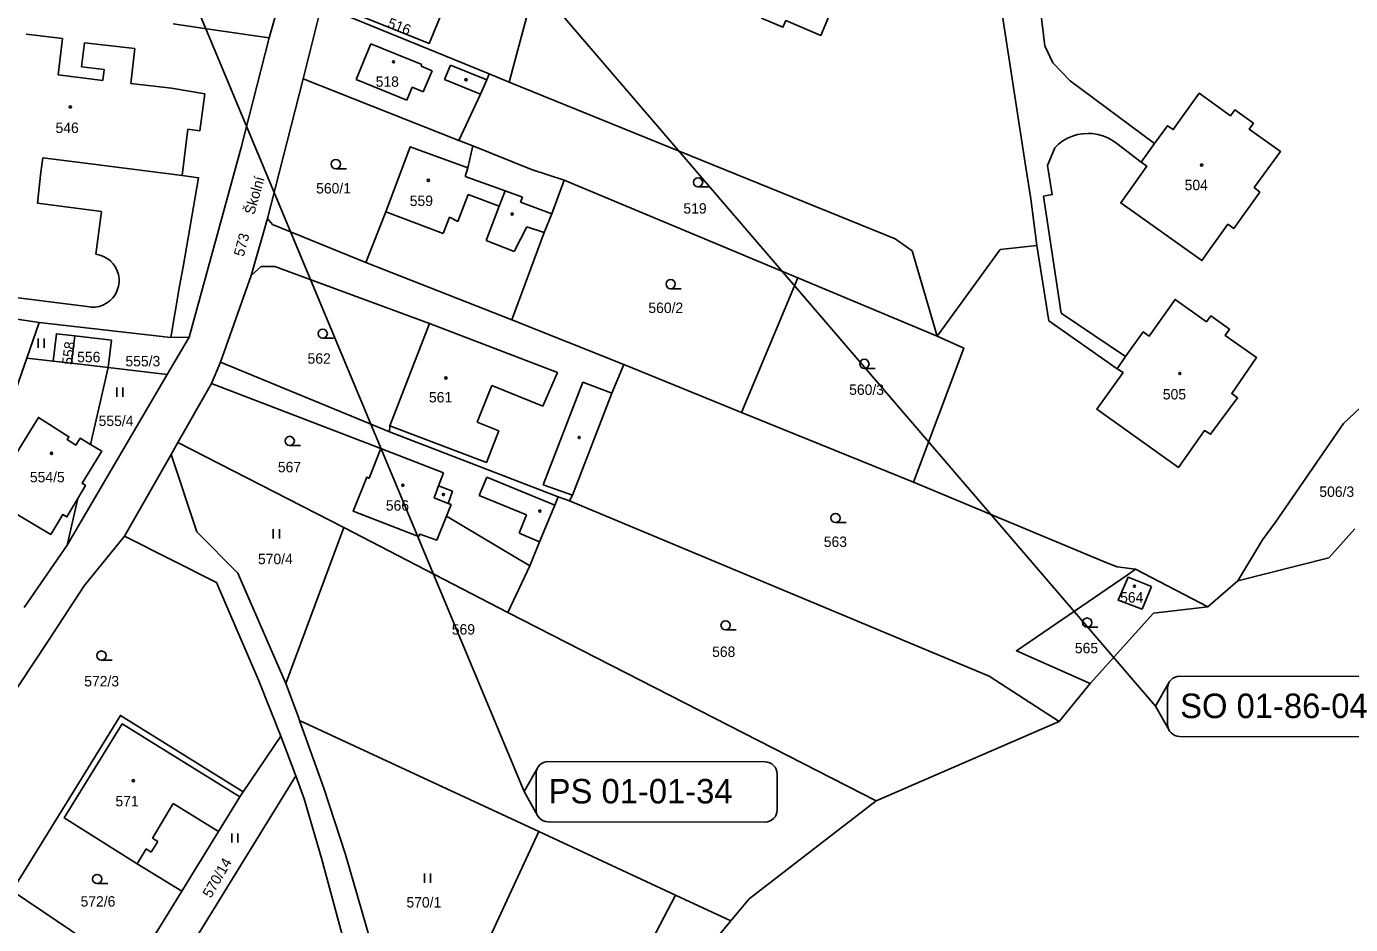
# Model space of a CAD drawing. Extents: x -558500 to -557517, y -1073973 to -1073051.
# Drawn here: x -558126.2 to -557909.9, y -1073687.1 to -1073540.5 of the extents above; entities that cross this region are included whole.
import ezdxf

# ---------------------------------------------------------------- set-up
doc = ezdxf.new("R2010")
doc.units = 0
for name, color, linetype in [('Hranice parcel', 7, 'Continuous'), ('Parcelní čísla', 7, 'Continuous'), ('Pop  PČ popisy', 7, 'Continuous'), ('Vnitřní kresba', 7, 'Continuous'), ('Vrstva 28', 7, 'Continuous'), ('Značky budov', 7, 'Continuous'), ('Značky kultur', 7, 'Continuous')]:
    doc.layers.add(name, color=color, linetype=linetype)

msp = doc.modelspace()

# ---------------------------------------------------------------- linework, layer by layer
at = {"layer": 'Hranice parcel'}
for p, q in [((-558079.12, -1073516.08), (-558086.54, -1073542.34)), ((-558078.01, -1073537.04), (-558080.96, -1073549.01)), ((-558078.01, -1073537.04), (-558050.57, -1073548.21)), ((-558080.96, -1073549.01), (-558086.83, -1073571.83)), ((-558080.96, -1073549.01), (-558055.56, -1073559.09)), ((-558050.57, -1073548.21), (-558047.33, -1073549.53)), ((-558055.56, -1073559.09), (-558053.26, -1073559.97)), ((-557944.07, -1073562.64), (-557948.05, -1073559.56)), ((-557941.9, -1073559.58), (-557944.07, -1073562.64)), ((-558038.36, -1073565.55), (-558000.16, -1073581.51)), ((-558086.83, -1073571.83), (-558089.47, -1073581.15)), ((-558070.72, -1073578.99), (-558046.87, -1073588.38)), ((-558089.47, -1073581.15), (-558094.5, -1073595.31)), ((-558009.36, -1073603.49), (-558000.16, -1073581.51)), ((-558000.16, -1073581.51), (-557977.41, -1073591.02)), ((-558169.56, -1073582.12), (-558124.1, -1073588.8)), ((-558146.72, -1073582.31), (-558116.26, -1073586.22)), ((-558046.87, -1073588.38), (-558028.58, -1073595.68)), ((-558124.1, -1073588.8), (-558126.13, -1073594.62)), ((-558124.1, -1073588.8), (-558102.62, -1073591.27)), ((-558118.29, -1073590.98), (-558118.81, -1073595.47)), ((-558099.6, -1073591.18), (-558103.17, -1073597.28)), ((-558102.62, -1073591.27), (-558099.6, -1073591.18)), ((-558121.8, -1073595.12), (-558126.13, -1073594.62)), ((-557946.67, -1073594.38), (-557948, -1073596.35)), ((-558121.8, -1073595.12), (-558118.81, -1073595.47)), ((-558118.81, -1073595.47), (-558112.83, -1073596.16)), ((-558115.73, -1073608.72), (-558112.83, -1073596.16)), ((-558112.83, -1073596.16), (-558103.17, -1073597.28)), ((-558094.5, -1073595.31), (-558095.93, -1073598.78)), ((-558094.5, -1073595.31), (-558066.88, -1073606.68)), ((-558028.58, -1073595.68), (-558009.36, -1073603.49)), ((-558103.17, -1073597.28), (-558119.53, -1073625.2)), ((-558095.93, -1073598.78), (-558101.44, -1073608.4)), ((-557981.3, -1073614.89), (-558009.36, -1073603.49)), ((-558066.88, -1073606.68), (-558039.3, -1073617.26)), ((-558101.44, -1073608.4), (-558102.56, -1073610.37)), ((-558101.44, -1073608.4), (-558074.34, -1073622.3)), ((-558102.56, -1073610.37), (-558110.18, -1073623.69)), ((-558119.53, -1073625.2), (-558117.76, -1073617.53)), ((-558039.3, -1073617.26), (-558037.5, -1073617.95)), ((-558074.34, -1073622.3), (-558083.83, -1073647.78)), ((-558074.34, -1073622.3), (-558047.53, -1073636.2)), ((-557909.21, -1073622.51), (-557913.41, -1073627.25)), ((-558119.53, -1073625.2), (-558126.57, -1073635.37)), ((-557913.41, -1073627.25), (-557928.28, -1073631.02)), ((-558047.53, -1073636.2), (-558043.97, -1073628.57)), ((-557933.2, -1073635.23), (-557945.03, -1073629.08)), ((-558083.83, -1073647.78), (-558091.67, -1073629.76)), ((-557928.28, -1073631.02), (-557933.2, -1073635.23)), ((-557942.08, -1073636.31), (-557933.2, -1073635.23)), ((-558047.53, -1073636.2), (-557987.38, -1073666.93)), ((-557952.42, -1073647.76), (-557942.08, -1073636.31)), ((-558083.83, -1073647.78), (-558081.75, -1073653.27)), ((-557957.49, -1073653.98), (-557952.42, -1073647.76)), ((-558081.75, -1073653.27), (-558081.56, -1073653.8)), ((-558081.56, -1073653.8), (-558042.48, -1073671.96)), ((-557987.38, -1073666.93), (-557957.49, -1073653.98)), ((-558084.61, -1073656.37), (-558090.78, -1073665.45)), ((-558084.61, -1073656.37), (-558082.19, -1073662.86)), ((-558082.19, -1073662.86), (-558103.95, -1073698.19)), ((-558082.19, -1073662.86), (-558080.79, -1073666.61)), ((-558090.78, -1073665.45), (-558091.34, -1073666.27)), ((-558008.13, -1073682.96), (-557987.38, -1073666.93)), ((-558058.98, -1073707.44), (-558042.48, -1073671.96)), ((-558042.48, -1073671.96), (-558020.18, -1073682.32)), ((-558114.13, -1073691.34), (-558128.54, -1073681.64)), ((-558100.81, -1073681.69), (-558108.93, -1073694.83)), ((-558020.18, -1073682.32), (-558039.55, -1073719.63)), ((-558020.18, -1073682.32), (-558011.11, -1073686.54)), ((-558011.11, -1073686.54), (-558008.13, -1073682.96)), ((-558017.53, -1073694.23), (-558011.11, -1073686.54))]:
    msp.add_line(p, q, dxfattribs=at)
for points in [[(-557875.08, -1073418.52), (-557880.11, -1073415), (-557884.66, -1073414.11), (-557888.78, -1073417.07), (-557919.08, -1073460.09), (-557919.51, -1073465.45), (-557958.15, -1073519.56), (-557960.76, -1073525.37), (-557961.25, -1073531.9), (-557959.85, -1073543.64), (-557958.52, -1073546.41), (-557955.67, -1073549.33), (-557941.9, -1073559.58)], [(-558047.33, -1073549.53), (-558040.31, -1073523.33), (-558072, -1073513.63)], [(-558008.57, -1073528.8), (-558011.42, -1073535.59), (-558005.63, -1073538.02), (-558006.1, -1073539.13), (-558002.62, -1073540.59), (-558002.16, -1073539.49), (-557996.41, -1073541.91), (-557993.56, -1073535.14), (-557992.45, -1073535.6), (-557989.61, -1073528.81), (-557990.71, -1073528.34), (-557987.91, -1073521.54), (-558002.9, -1073515.24), (-558005.74, -1073522.02), (-558006.84, -1073521.56), (-558009.68, -1073528.33), (-558008.57, -1073528.8)], [(-557961.12, -1073576.24), (-557962.13, -1073568.62), (-557962.94, -1073563.5), (-557966.76, -1073538.79), (-557967.76, -1073526.9)], [(-558058.43, -1073538.53), (-558065.06, -1073535.79), (-558065.61, -1073537.16), (-558072.15, -1073534.51), (-558073.59, -1073537.94), (-558060.37, -1073543.23), (-558058.43, -1073538.53)], [(-558086.54, -1073542.34), (-558095.62, -1073541.02), (-558102.24, -1073540.03)], [(-558099.6, -1073591.18), (-558091.09, -1073560.2), (-558086.54, -1073542.34)], [(-558055.56, -1073559.09), (-558052.02, -1073551.52), (-558051, -1073549.15), (-558050.57, -1073548.21)], [(-557977.41, -1073591.02), (-557981.5, -1073577.12), (-557984.25, -1073575.17), (-558047.33, -1073549.53)], [(-557944.07, -1073562.64), (-557943.15, -1073563.3), (-557947.42, -1073569.28), (-557934.16, -1073578.7), (-557929.93, -1073572.77), (-557928.96, -1073573.46), (-557924.72, -1073567.52), (-557925.63, -1073566.74), (-557921.33, -1073560.9), (-557926.44, -1073557.23), (-557925.76, -1073556.27), (-557928.81, -1073554.08), (-557929.5, -1073555.03), (-557934.61, -1073551.36), (-557938.85, -1073557.29), (-557939.81, -1073556.68), (-557941.9, -1073559.58)], [(-557948.05, -1073559.56), (-557948.76, -1073559.06), (-557949.52, -1073558.64), (-557950.33, -1073558.32), (-557951.17, -1073558.09), (-557952.03, -1073557.96), (-557952.77, -1073557.92), (-557953.64, -1073557.97), (-557954.49, -1073558.12), (-557955.32, -1073558.37), (-557956.12, -1073558.72), (-557956.88, -1073559.15), (-557957.57, -1073559.67), (-557958.21, -1073560.26)], [(-558053.26, -1073559.97), (-558054.09, -1073563.56), (-558063.5, -1073560.11), (-558067.45, -1073570.76), (-558070.72, -1073578.99)], [(-558053.26, -1073559.97), (-558043.68, -1073563.84), (-558038.36, -1073565.55)], [(-557958.21, -1073560.26), (-557959.37, -1073563.14), (-557958.62, -1073567.93), (-557960.03, -1073568.18), (-557957.14, -1073587.26), (-557946.67, -1073594.38)], [(-558124.4, -1073569.34), (-558123.84, -1073564.23), (-558123.49, -1073561.94), (-558118.73, -1073562.49), (-558100.77, -1073564.79), (-558098.05, -1073565.18), (-558100.59, -1073579.72), (-558101.17, -1073582.9), (-558102.62, -1073591.27)], [(-558046.87, -1073588.38), (-558041.59, -1073574.1), (-558040.35, -1073571.05), (-558038.36, -1073565.55)], [(-558114.83, -1073577.66), (-558113.93, -1073570.69), (-558124.4, -1073569.34)], [(-558086.83, -1073571.83), (-558085.98, -1073572.82), (-558070.72, -1073578.99)], [(-558116.26, -1073586.22), (-558115.61, -1073586.3), (-558114.95, -1073586.29), (-558114.3, -1073586.17), (-558113.68, -1073585.96), (-558113.09, -1073585.66), (-558112.56, -1073585.27), (-558112.09, -1073584.8), (-558111.7, -1073584.27), (-558111.4, -1073583.69), (-558111.18, -1073583.06), (-558111.15, -1073582.95), (-558111.05, -1073582.3), (-558111.05, -1073581.64), (-558111.15, -1073580.99), (-558111.35, -1073580.36), (-558111.64, -1073579.77), (-558112.02, -1073579.22), (-558112.47, -1073578.75), (-558112.99, -1073578.34), (-558113.57, -1073578.02), (-558114.19, -1073577.79), (-558114.83, -1073577.66)], [(-557977.41, -1073591.02), (-557967.12, -1073576.88), (-557961.12, -1073576.24)], [(-557948, -1073596.35), (-557959.17, -1073588.51), (-557961.12, -1073576.24)], [(-558089.47, -1073581.15), (-558087.83, -1073579.66), (-558085.58, -1073579.68), (-558060.36, -1073588.97), (-558066.81, -1073605.67), (-558066.88, -1073606.68)], [(-557948, -1073596.35), (-557947.05, -1073596.99), (-557951.31, -1073602.98), (-557937.98, -1073612.48), (-557933.77, -1073606.45), (-557932.74, -1073607.06), (-557928.33, -1073601.14), (-557929.29, -1073600.42), (-557925.23, -1073594.55), (-557930.39, -1073590.91), (-557929.67, -1073589.92), (-557932.7, -1073587.73), (-557933.42, -1073588.7), (-557938.54, -1073585.03), (-557942.77, -1073591.03), (-557943.74, -1073590.35), (-557946.67, -1073594.38)], [(-558118.29, -1073590.98), (-558121.28, -1073590.64), (-558121.8, -1073595.12)], [(-558112.83, -1073596.16), (-558112.31, -1073591.67), (-558118.29, -1073590.98)], [(-557981.3, -1073614.89), (-557973.04, -1073593.02), (-557977.41, -1073591.02)], [(-557928.28, -1073631.02), (-557924.28, -1073624.29), (-557922.14, -1073621.4), (-557911.04, -1073605.28), (-557897.48, -1073592.57)], [(-558126.13, -1073594.62), (-558131.94, -1073611.23), (-558141.92, -1073620.28)], [(-558037.5, -1073617.95), (-558036.99, -1073617), (-558030.56, -1073600.34), (-558028.58, -1073595.68)], [(-558095.93, -1073598.78), (-558068.28, -1073609.38), (-558070.18, -1073614.23), (-558070.6, -1073614.06), (-558072.8, -1073619.63), (-558062.12, -1073623.77), (-558061.94, -1073623.36), (-558059.17, -1073624.37), (-558057.59, -1073620.43), (-558043.97, -1073628.57)], [(-558117.76, -1073617.53), (-558119.58, -1073620.56), (-558120.26, -1073620.18), (-558122.2, -1073623.43), (-558129.88, -1073618.85), (-558127.67, -1073615.2), (-558130.05, -1073613.78), (-558124.22, -1073604.32), (-558119.25, -1073607.46), (-558119.52, -1073607.94), (-558118.12, -1073608.84), (-558117.4, -1073607.72), (-558115.73, -1073608.72)], [(-558115.73, -1073608.72), (-558113.89, -1073609.83), (-558117.1, -1073615.05), (-558116.51, -1073615.45), (-558117.76, -1073617.53)], [(-558091.67, -1073629.76), (-558098.34, -1073623.01), (-558102.56, -1073610.37)], [(-557945.03, -1073629.08), (-557947.99, -1073628.74), (-557949.68, -1073628.07), (-557981.3, -1073614.89)], [(-558043.97, -1073628.57), (-558042.35, -1073624.63), (-558039.87, -1073618.65), (-558039.3, -1073617.26)], [(-558037.5, -1073617.95), (-557968.93, -1073646.57), (-557957.49, -1073653.98)], [(-558143.16, -1073671.79), (-558122.68, -1073640.91), (-558116.74, -1073631.82), (-558110.18, -1073623.69)], [(-558110.18, -1073623.69), (-558095.16, -1073631.27), (-558088.2, -1073647.35), (-558084.61, -1073656.37)], [(-557952.42, -1073647.76), (-557964.47, -1073642.42), (-557946.38, -1073630.08), (-557945.03, -1073629.08)], [(-557942.43, -1073631.91), (-557946.23, -1073630.43), (-557947.87, -1073634.18), (-557943.94, -1073635.62), (-557942.43, -1073631.91)], [(-558128.54, -1073681.64), (-558110.84, -1073652.98), (-558090.78, -1073665.45)], [(-558091.34, -1073666.27), (-558110.52, -1073654.36), (-558120.01, -1073669.73), (-558108.1, -1073677.21), (-558100.81, -1073681.69)], [(-558081.56, -1073653.8), (-558077.6, -1073664.88), (-558074.09, -1073675.7), (-558068.03, -1073696.59), (-558066.56, -1073700.76), (-558064.34, -1073704.08), (-558058.98, -1073707.44)], [(-558100.81, -1073681.69), (-558094.8, -1073671.95), (-558091.34, -1073666.27)], [(-558080.79, -1073666.61), (-558077.98, -1073676.29), (-558072.03, -1073698.27), (-558070.37, -1073702.74), (-558067.15, -1073708.5), (-558060.97, -1073713.55), (-558050.8, -1073719.38), (-558037.27, -1073726.47), (-558036.33, -1073723.21), (-558032.62, -1073725.69)]]:
    msp.add_lwpolyline(points, dxfattribs=at)
at = {"layer": 'Vnitřní kresba'}
for p, q in [((-558126.22, -1073541.7), (-558120.27, -1073542.43)), ((-558121, -1073548.38), (-558120.27, -1073542.43)), ((-558117.17, -1073547.04), (-558116.72, -1073543.11)), ((-558116.72, -1073543.11), (-558108.48, -1073544.08)), ((-558109.12, -1073549.75), (-558108.48, -1073544.08)), ((-558072.33, -1073549.11), (-558069.95, -1073543.28)), ((-558069.95, -1073543.28), (-558061.62, -1073546.69)), ((-558117.17, -1073547.04), (-558113.48, -1073547.47)), ((-558061.73, -1073546.96), (-558061.62, -1073546.69)), ((-558061.73, -1073546.96), (-558059.91, -1073547.71)), ((-558057.87, -1073549.14), (-558056.91, -1073546.78)), ((-558056.91, -1073546.78), (-558051, -1073549.15)), ((-558121, -1073548.38), (-558113.69, -1073549.26)), ((-558113.69, -1073549.26), (-558113.48, -1073547.47)), ((-558072.33, -1073549.11), (-558064.04, -1073552.48)), ((-558061.37, -1073551.16), (-558059.91, -1073547.71)), ((-558057.87, -1073549.14), (-558052.02, -1073551.52)), ((-558109.12, -1073549.75), (-558102.5, -1073550.54)), ((-558102.5, -1073550.54), (-558097.04, -1073551.46)), ((-558097.85, -1073557.5), (-558097.04, -1073551.46)), ((-558064.04, -1073552.48), (-558063.17, -1073550.4)), ((-558063.17, -1073550.4), (-558061.37, -1073551.16)), ((-558100.77, -1073564.79), (-558099.8, -1073557.24)), ((-558099.8, -1073557.24), (-558097.85, -1073557.5)), ((-558054.51, -1073564.95), (-558054.09, -1073563.56)), ((-558054.51, -1073564.95), (-558048, -1073567.3)), ((-558055.72, -1073572.3), (-558054.04, -1073567.93)), ((-558054.04, -1073567.93), (-558048.94, -1073569.79)), ((-558048.94, -1073569.79), (-558048, -1073567.3)), ((-558048, -1073567.3), (-558045.17, -1073568.34)), ((-558045.48, -1073569.18), (-558045.17, -1073568.34)), ((-558067.45, -1073570.76), (-558058.09, -1073574.3)), ((-558051.08, -1073575.44), (-558048.94, -1073569.79)), ((-558045.48, -1073569.18), (-558040.35, -1073571.05)), ((-558058.09, -1073574.3), (-558057.1, -1073571.59)), ((-558057.1, -1073571.59), (-558055.72, -1073572.3)), ((-558046.52, -1073577.2), (-558044.47, -1073573.2)), ((-558044.47, -1073573.2), (-558041.59, -1073574.1)), ((-558051.08, -1073575.44), (-558046.52, -1073577.2)), ((-558060.36, -1073588.97), (-558039.44, -1073597)), ((-558041.81, -1073602.48), (-558039.44, -1073597)), ((-558052.58, -1073605.08), (-558050.15, -1073599.12)), ((-558050.15, -1073599.12), (-558041.81, -1073602.48)), ((-558041.75, -1073615.33), (-558035.32, -1073598.58)), ((-558035.32, -1073598.58), (-558030.56, -1073600.34)), ((-558066.81, -1073605.67), (-558051.04, -1073611.69)), ((-558052.58, -1073605.08), (-558049.01, -1073606.53)), ((-558051.04, -1073611.69), (-558049.01, -1073606.53)), ((-558068.28, -1073609.38), (-558058.04, -1073613.34)), ((-558058.85, -1073615.47), (-558058.04, -1073613.34)), ((-558052.22, -1073617.07), (-558050.97, -1073614.06)), ((-558050.97, -1073614.06), (-558039.87, -1073618.65)), ((-558059.56, -1073617.45), (-558058.85, -1073615.47)), ((-558058.85, -1073615.47), (-558056.6, -1073616.37)), ((-558057.32, -1073618.35), (-558056.6, -1073616.37)), ((-558041.75, -1073615.33), (-558036.99, -1073617)), ((-558059.56, -1073617.45), (-558057.32, -1073618.35)), ((-558057.59, -1073620.43), (-558056.83, -1073618.55)), ((-558057.32, -1073618.35), (-558056.83, -1073618.55)), ((-558052.22, -1073617.07), (-558044.49, -1073620.2)), ((-558045.71, -1073623.2), (-558044.49, -1073620.2)), ((-558045.71, -1073623.2), (-558042.35, -1073624.63)), ((-558105.6, -1073673.04), (-558102.19, -1073667.36)), ((-558102.19, -1073667.36), (-558094.8, -1073671.95)), ((-558108.1, -1073677.21), (-558106.65, -1073674.8)), ((-558106.65, -1073674.8), (-558105.79, -1073675.32)), ((-558105.79, -1073675.32), (-558104.74, -1073673.55)), ((-558105.6, -1073673.04), (-558104.74, -1073673.55))]:
    msp.add_line(p, q, dxfattribs=at)
at = {"layer": 'Vrstva 28'}
for p, q in [((-558150.5, -1073408.33), (-557941.76, -1073651.48)), ((-558150.16, -1073413.05), (-558044.9, -1073665.43)), ((-557937.81, -1073646.57), (-557902.38, -1073646.62)), ((-557941.76, -1073651.48), (-557939.53, -1073647.56)), ((-557939.79, -1073654.44), (-557939.78, -1073648.53)), ((-557939.54, -1073655.41), (-557941.76, -1073651.48)), ((-557902.39, -1073656.47), (-557937.83, -1073656.41)), ((-558044.9, -1073665.43), (-558042.67, -1073661.51)), ((-558040.96, -1073660.51), (-558005.53, -1073660.57)), ((-558042.94, -1073668.38), (-558042.93, -1073662.48)), ((-558003.56, -1073662.54), (-558003.57, -1073668.45)), ((-558042.68, -1073669.35), (-558044.9, -1073665.43)), ((-558005.54, -1073670.41), (-558040.97, -1073670.36))]:
    msp.add_line(p, q, dxfattribs=at)
for centre, start, end in [((-557937.81, -1073648.54), 89.9095, 179.9095), ((-557937.82, -1073654.44), 179.9095, 269.9095), ((-558040.96, -1073662.48), 89.9095, 179.9095), ((-558005.53, -1073662.54), 359.9095, 89.9095), ((-558040.97, -1073668.39), 179.9095, 269.9095), ((-558005.54, -1073668.44), 269.9095, 359.9095)]:
    msp.add_arc(centre, 1.97, start, end, dxfattribs=at)
at = {"layer": 'Značky budov'}
for centre in [(-558066.22, -1073546.23), (-558054.38, -1073549.16), (-558119.02, -1073553.6), (-557934.21, -1073563.1), (-558060.53, -1073565.58), (-558046.85, -1073571.1), (-557937.77, -1073597.13), (-558057.66, -1073597.88), (-558035.89, -1073607.59), (-558122.08, -1073610.17), (-558064.7, -1073615.39), (-558058.07, -1073616.9), (-558042.33, -1073619.61), (-557945.18, -1073631.87), (-558108.71, -1073663.65)]:
    msp.add_circle(centre, 0.175, dxfattribs=at)
at = {"layer": 'Značky kultur'}
for p, q in [((-558075.65, -1073563.69), (-558073.9, -1073563.69)), ((-558016.47, -1073566.66), (-558014.72, -1073566.66)), ((-558020.96, -1073583.29), (-558019.21, -1073583.29)), ((-558124.27, -1073592.93), (-558124.27, -1073591.43)), ((-558123.27, -1073592.93), (-558123.27, -1073591.43)), ((-558077.78, -1073591.38), (-558076.03, -1073591.38)), ((-557989.3, -1073596.32), (-557987.55, -1073596.32)), ((-558111.42, -1073600.94), (-558111.42, -1073599.44)), ((-558110.42, -1073600.94), (-558110.42, -1073599.44)), ((-558083.17, -1073608.9), (-558081.42, -1073608.9)), ((-558085.87, -1073624.09), (-558085.87, -1073622.59)), ((-558084.87, -1073624.09), (-558084.87, -1073622.59)), ((-557994.02, -1073621.49), (-557992.27, -1073621.49)), ((-558011.98, -1073639.01), (-558010.23, -1073639.01)), ((-557952.92, -1073638.57), (-557951.17, -1073638.57)), ((-558113.93, -1073643.96), (-558112.18, -1073643.96)), ((-558092.63, -1073673.76), (-558092.63, -1073672.26)), ((-558091.63, -1073673.76), (-558091.63, -1073672.26)), ((-558061.16, -1073680.32), (-558061.16, -1073678.82)), ((-558060.16, -1073680.32), (-558060.16, -1073678.82)), ((-558114.63, -1073680.46), (-558112.88, -1073680.46))]:
    msp.add_line(p, q, dxfattribs=at)
for centre in [(-558075.65, -1073562.94), (-558016.47, -1073565.91), (-558020.96, -1073582.54), (-558077.78, -1073590.63), (-557989.3, -1073595.57), (-558083.17, -1073608.15), (-557994.02, -1073620.74), (-558011.98, -1073638.26), (-557952.92, -1073637.82), (-558113.93, -1073643.21), (-558114.63, -1073679.71)]:
    msp.add_circle(centre, 0.75, dxfattribs=at)

# ---------------------------------------------------------------- texts
at = {"layer": 'Parcelní čísla'}
for s, rotation, p in [('516', 339, (-558067.34, -1073540.57)), ('573', 75, (-558090.71, -1073578.15)), ('558', 83, (-558118.7, -1073595.8)), ('570/14', 60, (-558096.05, -1073682.93))]:
    msp.add_text(s, height=1.7, rotation=rotation, dxfattribs=at).set_placement(p)
for s, p in [('518', (-558069.13, -1073550.31)), ('546', (-558121.43, -1073557.86)), ('560/1', (-558078.86, -1073567.74)), ('504', (-557936.99, -1073567.2)), ('559', (-558063.57, -1073569.78)), ('519', (-558018.87, -1073571.02)), ('560/2', (-558024.59, -1073587.26)), ('556', (-558117.9, -1073595.3)), ('555/3', (-558110.01, -1073595.97)), ('562', (-558080.26, -1073595.54)), ('560/3', (-557991.79, -1073600.63)), ('561', (-558060.43, -1073601.87)), ('505', (-557940.55, -1073601.38)), ('555/4', (-558114.39, -1073605.72)), ('567', (-558085.11, -1073613.27)), ('554/5', (-558125.62, -1073614.91)), ('506/3', (-557914.99, -1073617.29)), ('566', (-558067.47, -1073619.54)), ('563', (-557995.94, -1073625.47)), ('570/4', (-558088.36, -1073628.28)), ('564', (-557947.53, -1073634.55)), ('569', (-558056.7, -1073639.78)), ('568', (-558014.18, -1073643.43)), ('565', (-557954.92, -1073642.83)), ('572/3', (-558116.74, -1073648.25)), ('571', (-558111.64, -1073667.83)), ('572/6', (-558117.34, -1073684.21)), ('570/1', (-558064.11, -1073684.36))]:
    msp.add_text(s, height=1.7, dxfattribs=at).set_placement(p)
at = {"layer": 'Pop  PČ popisy'}
msp.add_text('Školní', height=1.7, rotation=74, dxfattribs=at).set_placement((-558088.99, -1073571.32))
at = {"layer": 'Vrstva 28'}
for s, p in [('SO 01-86-04', (-557937.72, -1073653.42)), ('PS 01-01-34', (-558040.87, -1073667.36))]:
    msp.add_text(s, height=4, dxfattribs=at).set_placement(p)

doc.saveas('drawing.dxf')
